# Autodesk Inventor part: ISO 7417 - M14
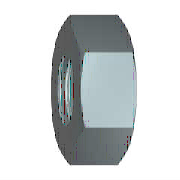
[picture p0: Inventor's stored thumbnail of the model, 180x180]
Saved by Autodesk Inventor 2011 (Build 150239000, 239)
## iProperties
Created: 2009-02
Part Number: ISO 7417 - M14
Material: Steel
Description: Hexagon nuts for structural bolting, style 2, hot-dip galvanized (oversize tapped) - Product grade A - Property class 9
Document SubType Name: Modeling
Standard: ISO 7417
Designer: 904Chiaki
Standard Revision: First edition 1984-11-15
Standards Organization: ISO
Language: en-US
Size Designation: M14
Categories: <MemberInstance><Categories><Category DisplayName="Fasteners" InternalName="e4da775c-781d-43d5-af7c-5136215cf5a6" Mnemonic="FSTN"><Category DisplayName="Nuts" I
Density: 7.85 g/cm^3
Mass: 29.36 g
Surface Area: 19.8016 cm^2
Volume: 3.74013 cm^3
IsCustomPart: 0
Author: 904Chiaki
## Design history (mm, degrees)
body "Solid1"
workaxis "Work Axis1"
workplane "Work Plane1"
sketch "Sketch1"
  geometry: L1 (-12.124, 0)-(-6.062, 10.5); L2 (-6.062, 10.5)-(6.062, 10.5); L3 (6.062, 10.5)-(12.124, 0); L4 (12.124, 0)-(6.062, -10.5); L5 (6.062, -10.5)-(-6.062, -10.5); L6 (-6.062, -10.5)-(-12.124, 0); 2 further points
  constraints: 12 end point, 1 coincident, 1 horizontal, 11 other
  dimensions: "d0" = 24.24871 distance of L3.end L1.start (= 1.1547 x SW)
extrude "Body" new body sketch "Sketch1" distance "d1" = 14.1 (= KOH); taper "d2" = 0 deg
revolve "Chamfer1" stored, may be unused: angle "d7" = 90 deg
sketch "Sketch3"
  geometry: 4 further points
  constraints: 1 coincident, 1 other
hole "Thread" sketch "Sketch3" diameter "d25" = 11.835; stored, may be unused: countersink angle "d29" = 82 deg, drill point angle "d31" = 118 deg; dims "d26" = 6, "d27" = 4, "d28" = 2, "d30" = 8
chamfer "Chamfer2" distance "d8" = 1.08253 (= -0.5 x GD1 + 0.5 x NND); stored, may be unused: angle "d9" = 30 deg, second distance "d40" = 1.08253 (= -0.5 x GD1 + 0.5 x NND)
chamfer "Chamfer3" distance "d10" = 1.08253 (= -0.5 x GD1 + 0.5 x NND); stored, may be unused: angle "d11" = 30 deg, second distance "d41" = 1.08253 (= -0.5 x GD1 + 0.5 x NND)
sketch "Sketch2"
  geometry: L1 (0, 6.062)-(0, 12.124) reference; L2 (0, 12.124)-(14.1, 12.124) reference; L3 (14.1, 6.062)-(14.1, 12.124) reference; L4 (-2.82, 0)-(16.92, 0) reference; L5 (1.342, 12.124)-(0, 9.8); L6 (12.758, 12.124)-(14.1, 9.8)
  constraints: 4 end point, 4 point on line
  dimensions: "d3" = 30 deg angle of L1 L5 (= ANG1); "d4" = 30 deg angle of L3 L6 (= ANG2); "d5" = 19.6 diameter of L5.end L4 (= SW0); "d6" = 19.6 diameter of L6.end L4 (= SW01)
other parameters: "ANG1" = 30 deg [user parameter; used in 1 equation term], "ANG2" = 30 deg [user parameter; used in 1 equation term], "NND" = 14 [user parameter; used in 4 equation terms], "KOH" = 14.1 [user parameter; used in 1 equation term], "SW" = 21 [user parameter; used in 2 equation terms], "SW0" = 19.6 [user parameter; used in 2 equation terms], "SW01" = 19.6 (= SW0) [user parameter; used in 1 equation term], "GD1" = 11.83494 (computed from THREADDIA, PTC, TOA) [user parameter; used in 4 equation terms], "d13" = 0, "d14" = 0, "d39" = 0, "d42" = 0, "GUL" = 1.08253 (= 0.541266 x PTC) [user parameter], "TPU" = 5 (computed from PTC) [user parameter], "THREADDIA" = 14 [user parameter; used in 1 equation term], "TOA" = 30 deg [user parameter; used in 1 equation term], "PTC" = 2 [user parameter; used in 4 equation terms], "E0" = 24.255 (= 1.155 x SW) [user parameter], "GAL" = 1.08253 (= 0.541266 x PTC) [user parameter], "KOH1" = 10.7 [user parameter]
